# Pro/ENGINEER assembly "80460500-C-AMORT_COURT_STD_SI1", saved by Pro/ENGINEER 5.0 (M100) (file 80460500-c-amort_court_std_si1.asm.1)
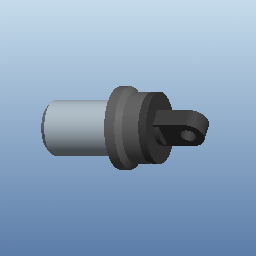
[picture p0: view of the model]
Units: millimeter Newton Second (mmNs); MM, TONNE, HOURS

Other components: 80460500-C-AMORT_COURT_STD_SI1, 80160500-BOUCHON_AMORT-STD_SI1

Other named items: 80460500-C-AMORT_COURT_STD_01, 80160500-BOUCHON_AMORT-STD_01, A-DROITE, A-DESSUS, A-FACE, A-R0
